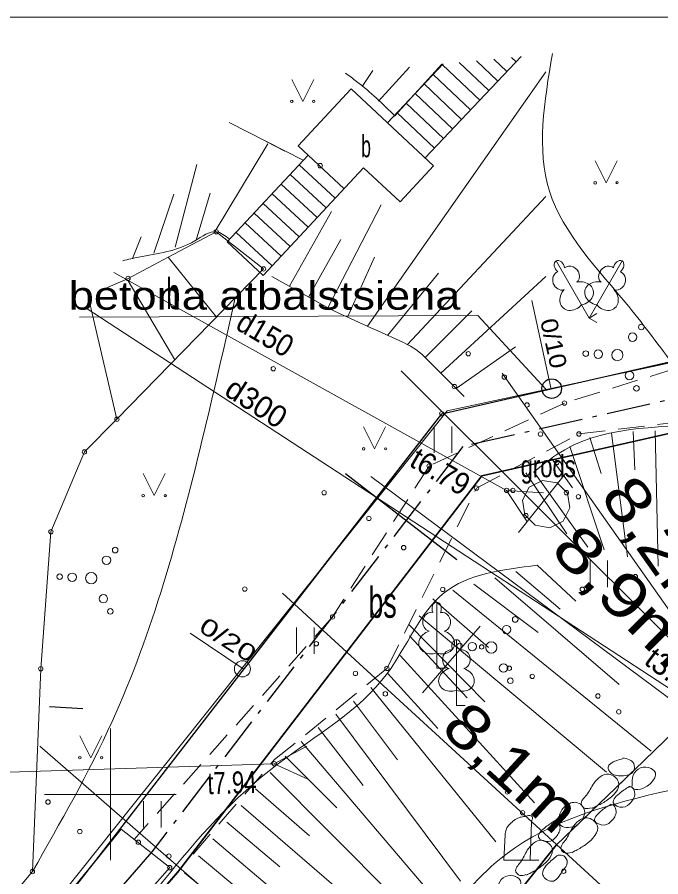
# Model space of a CAD drawing. Extents: x -1271.1 to -1218.8, y 769 to 838.3.
# Drawn here: x -1247.62 to -1232.98, y 818.71 to 838.28 of the extents above; entities that cross this region are included whole.
import ezdxf
from ezdxf.enums import TextEntityAlignment as Align

# ---------------------------------------------------------------- set-up
doc = ezdxf.new("R2010")
doc.units = 0
doc.header["$LTSCALE"] = 0.2
doc.linetypes.add('DOT_DASHED', pattern=[7.7, 5, -1.2, 0.3, -1.2])
doc.linetypes.add('MEDIUM_DASHED', pattern=[4.5, 3, -1.5])
for name, color, linetype, lineweight in [('1', 7, 'Continuous', 13), ('19', 7, 'Continuous', 13), ('25', 7, 'Continuous', 13), ('28', 7, 'Continuous', 13), ('3', 7, 'Continuous', 13), ('30', 7, 'Continuous', 13), ('35', 7, 'Continuous', 25), ('5', 7, 'Continuous', 13), ('55', 7, 'Continuous', 13), ('56', 7, 'Continuous', 13), ('6', 7, 'Continuous', 13), ('61', 7, 'Continuous', 13), ('62', 7, 'Continuous', 13), ('63', 7, 'Continuous', 13)]:
    doc.layers.add(name, color=color, linetype=linetype, lineweight=lineweight)
for name, color, linetype in [('10', 7, 'Continuous'), ('11', 7, 'Continuous'), ('15', 7, 'Continuous')]:
    doc.layers.add(name, color=color, linetype=linetype)

msp = doc.modelspace()

# ---------------------------------------------------------------- linework, layer by layer
at = {"layer": '1'}
for p, q in [((-1239.776, 836.7), (-1239.532, 837.06)), ((-1239.406, 836.364), (-1238.704, 837.139)), ((-1239.036, 836.028), (-1237.965, 837.209)), ((-1239.653, 831.243), (-1235.601, 837.032)), ((-1243.118, 833.404), (-1241.924, 835.396)), ((-1244.033, 833.046), (-1243.542, 834.922)), ((-1244.513, 832.907), (-1244.059, 834.249)), ((-1243.557, 833.198), (-1243.234, 834.273)), ((-1238.745, 830.824), (-1235.601, 834.194)), ((-1240.56, 831.663), (-1239.347, 834.009)), ((-1241.432, 832.152), (-1240.476, 833.853)), ((-1244.998, 832.783), (-1244.803, 833.279)), ((-1240.996, 831.907), (-1240.261, 833.214)), ((-1240.109, 831.447), (-1239.498, 832.816)), ((-1239.198, 831.035), (-1238.041, 832.447)), ((-1237.99, 830.176), (-1235.601, 832.375)), ((-1235.485, 829.842), (-1235.921, 831.825)), ((-1238.343, 830.529), (-1237.283, 831.591)), ((-1237.636, 829.823), (-1236.293, 830.774)), ((-1238.894, 830.226), (-1231.002, 822.353)), ((-1228.446, 818.593), (-1236.594, 830.173)), ((-1233.61, 828.848), (-1233.573, 827.973)), ((-1233.11, 828.861), (-1233.048, 825.785)), ((-1234.598, 828.708), (-1234.344, 827.894)), ((-1234.109, 828.809), (-1233.743, 825.994)), ((-1235.054, 828.507), (-1234.271, 826.156)), ((-1235.464, 828.221), (-1234.996, 827.565)), ((-1235.871, 827.931), (-1234.647, 826.214)), ((-1239.581, 827.819), (-1230.198, 820.844)), ((-1235.8, 825.801), (-1234.915, 824.985)), ((-1236.759, 825.516), (-1233.93, 823.086)), ((-1236.28, 825.659), (-1235.273, 824.806)), ((-1237.238, 825.374), (-1235.775, 824.269)), ((-1241.586, 825.164), (-1230.918, 815.373)), ((-1237.718, 825.232), (-1233.202, 821.569)), ((-1238.174, 825.038), (-1236.903, 823.928)), ((-1238.484, 824.65), (-1234.223, 821.091)), ((-1242.465, 823.426), (-1243.688, 824.26)), ((-1238.698, 824.198), (-1237.386, 822.782)), ((-1238.91, 823.745), (-1235.858, 820.396)), ((-1239.205, 823.344), (-1238.058, 822.089)), ((-1239.583, 823.017), (-1236.735, 819.506)), ((-1239.977, 822.71), (-1238.971, 821.376)), ((-1240.377, 822.41), (-1237.544, 818.612)), ((-1240.776, 822.109), (-1239.755, 820.789)), ((-1241.164, 821.793), (-1238.014, 818.09)), ((-1247.111, 821.685), (-1235.538, 811.611)), ((-1241.532, 821.455), (-1240.352, 820.28)), ((-1241.871, 821.088), (-1238.432, 817.627)), ((-1242.202, 820.713), (-1240.977, 819.642)), ((-1242.53, 820.335), (-1238.852, 817.164)), ((-1242.855, 819.955), (-1241.653, 818.938)), ((-1243.178, 819.573), (-1239.485, 816.469)), ((-1243.499, 819.19), (-1242.327, 818.215)), ((-1243.818, 818.805), (-1240.142, 815.757))]:
    msp.add_line(p, q, dxfattribs=at)
msp.add_lwpolyline([(-1237.459, 829.646), (-1237.914, 830.1), (-1238.369, 830.555), (-1238.424, 830.606), (-1238.478, 830.651), (-1238.53, 830.691), (-1238.581, 830.726), (-1238.679, 830.787), (-1238.769, 830.837), (-1238.849, 830.877), (-1239.425, 831.137), (-1239.58, 831.21), (-1240.128, 831.455), (-1240.264, 831.517), (-1240.466, 831.615), (-1240.565, 831.666), (-1240.664, 831.72), (-1241.247, 832.048), (-1241.829, 832.375)], dxfattribs=at)
at = {"layer": '1', "lineweight": 25}
msp.add_circle((-1235.466, 829.823), 0.2224, dxfattribs=at)
at = {"layer": '1'}
msp.add_circle((-1242.502, 823.444), 0.1827, dxfattribs=at)
for points in [[(-1240.158, 837.001), (-1239.903, 836.815), (-1239.03, 836.023)], [(-1245.222, 832.735), (-1244.862, 832.816), (-1243.584, 833.187), (-1243.096, 833.394), (-1242.798, 833.227)], [(-1235.871, 827.931), (-1235.167, 828.433), (-1231.672, 829.028), (-1224.12, 831.442)], [(-1235.8, 825.801), (-1237.913, 825.174), (-1239.203, 823.346), (-1241.709, 821.268), (-1246.557, 815.58), (-1256.526, 805.053), (-1260.592, 799.147), (-1261.416, 795.29), (-1262.742, 791.444), (-1262.206, 785.139)]]:
    msp.add_spline(points, degree=3, dxfattribs=at)
at = {"layer": '19'}
msp.add_spline([(-1253.457, 785.393), (-1253.726, 794.104), (-1251.637, 801.373), (-1250.122, 804.26), (-1247.608, 807.348), (-1239.437, 815.545), (-1236.508, 819.221), (-1228.799, 821.851), (-1223.357, 826.161), (-1220.079, 827.95)], degree=3, dxfattribs=at)
at = {"layer": '25'}
for points in [[(-1245.505, 822.086), (-1245.505, 820.586), (-1245.505, 819.086)], [(-1245.505, 822.086), (-1245.505, 820.586), (-1245.505, 819.086)], [(-1247.005, 820.586), (-1245.505, 820.586), (-1244.005, 820.586)], [(-1247.005, 820.586), (-1245.505, 820.586), (-1244.005, 820.586)]]:
    msp.add_lwpolyline(points, dxfattribs=at)
at = {"layer": '28'}
for points in [[(-1235.654, 827.452), (-1236.491, 827.506), (-1236.033, 826.804)], [(-1241.04, 821.682), (-1241.778, 821.284), (-1241.017, 820.933)]]:
    msp.add_lwpolyline(points, dxfattribs=at)
at = {"layer": '3'}
for p, q in [((-1236.491, 827.506), (-1245.43, 832.464)), ((-1232.369, 822.724), (-1246.052, 831.654)), ((-1251.16, 820.99), (-1241.778, 821.284))]:
    msp.add_line(p, q, dxfattribs=at)
at = {"layer": '30'}
msp.add_spline([(-1247.278, 818.829), (-1245.467, 822.244), (-1243.421, 828.633), (-1242.663, 831.887)], degree=3, dxfattribs=at)
at = {"layer": '35'}
msp.add_lwpolyline([(-1264.692, 791.666), (-1263.121, 794.463), (-1262.995, 800.82), (-1256.407, 807.512), (-1249.819, 814.203), (-1245.888, 819.015), (-1242.275, 823.687), (-1240.604, 825.846), (-1237.968, 829.25), (-1236.511, 829.583), (-1228.03, 831.521)], dxfattribs=at)
at = {"layer": '35', "lineweight": 35}
msp.add_lwpolyline([(-1225.362, 830.487), (-1237.056, 827.834), (-1243.981, 818.809), (-1250.833, 810.905), (-1258.147, 803.474), (-1260.339, 800.099), (-1261.472, 796.156), (-1261.529, 794.093), (-1263.29, 790.894)], dxfattribs=at)
at = {"layer": '5'}
for p, q in [((-1235.366, 832.728), (-1234.79, 831.73)), ((-1235.172, 832.572), (-1235.174, 832.572)), ((-1233.866, 832.728), (-1234.443, 831.73)), ((-1233.905, 832.482), (-1233.905, 832.483)), ((-1234.79, 831.73), (-1234.616, 831.429)), ((-1234.443, 831.73), (-1234.616, 831.429)), ((-1234.616, 831.429), (-1234.443, 831.529)), ((-1234.616, 831.429), (-1234.443, 831.329)), ((-1238.137, 828.361), (-1238.137, 828.961)), ((-1237.737, 828.361), (-1237.737, 828.961)), ((-1234.594, 825.307), (-1234.594, 825.907)), ((-1234.194, 825.307), (-1234.194, 825.907)), ((-1238.083, 824.961), (-1238.083, 823.808)), ((-1237.993, 824.729), (-1237.994, 824.73)), ((-1241.27, 823.783), (-1241.27, 824.383)), ((-1240.87, 823.783), (-1240.87, 824.383)), ((-1237.633, 824.107), (-1237.633, 822.954)), ((-1238.083, 823.808), (-1238.083, 823.461)), ((-1237.543, 823.875), (-1237.544, 823.876)), ((-1238.083, 823.461), (-1237.883, 823.461)), ((-1237.633, 822.954), (-1237.633, 822.607)), ((-1237.633, 822.607), (-1237.433, 822.607)), ((-1244.748, 819.833), (-1244.748, 820.433)), ((-1244.348, 819.833), (-1244.348, 820.433)), ((-1235.958, 819.092), (-1235.924, 819.957)), ((-1235.958, 819.092), (-1236.558, 819.092)), ((-1235.958, 819.092), (-1235.758, 819.092))]:
    msp.add_line(p, q, dxfattribs=at)
for points in [[(-1241.378, 836.861), (-1241.128, 836.361), (-1240.878, 836.861)], [(-1234.477, 835.008), (-1234.227, 834.508), (-1233.977, 835.008)], [(-1239.744, 828.953), (-1239.494, 828.453), (-1239.244, 828.953)], [(-1244.758, 827.887), (-1244.508, 827.387), (-1244.258, 827.887)], [(-1246.2, 821.922), (-1245.95, 821.422), (-1245.7, 821.922)], [(-1236.527, 819.665), (-1236.558, 819.092), (-1236.258, 819.092), (-1235.958, 819.092)]]:
    msp.add_lwpolyline(points, dxfattribs=at)
for centre, radius in [((-1241.3784, 836.3607), 0.028), ((-1240.8784, 836.3607), 0.0263), ((-1234.4776, 834.5072), 0.028), ((-1233.9776, 834.5072), 0.0263), ((-1233.429, 831.2245), 0.064), ((-1233.6255, 830.9928), 0.096), ((-1234.6915, 830.6194), 0.064), ((-1234.407, 830.6059), 0.096), ((-1233.973, 830.5851), 0.128), ((-1233.6966, 830.1183), 0.096), ((-1233.5391, 829.829), 0.064), ((-1239.7447, 828.4523), 0.028), ((-1239.2447, 828.4523), 0.0263), ((-1244.7584, 827.3863), 0.028), ((-1244.2584, 827.3863), 0.0263), ((-1245.396, 826.1475), 0.064), ((-1245.5925, 825.9158), 0.096), ((-1246.6584, 825.5424), 0.064), ((-1246.374, 825.5289), 0.096), ((-1245.94, 825.5082), 0.128), ((-1245.6636, 825.0413), 0.096), ((-1245.5061, 824.752), 0.064), ((-1236.296, 824.5695), 0.064), ((-1236.4925, 824.3378), 0.096), ((-1237.5584, 823.9644), 0.064), ((-1237.274, 823.9509), 0.096), ((-1236.84, 823.9302), 0.128), ((-1236.5636, 823.4633), 0.096), ((-1236.4061, 823.174), 0.064), ((-1246.1999, 821.4214), 0.028), ((-1245.6999, 821.4214), 0.0263)]:
    msp.add_circle(centre, radius, dxfattribs=at)
for centre, major_axis, ratio, start_param, end_param in [((-1235.2914, 832.5981), (0.075, -0.1298), 0.707107, 0.9957007, 3.1378155), ((-1233.9407, 832.5981), (-0.075, -0.1298), 0.707107, 3.1453698, 5.2874846), ((-1235.2907, 832.5985), (0.075, -0.1298), 0.707107, 3.1453698, 5.2874846), ((-1235.0325, 832.4071), (0.1397, -0.1646), 0.861323, 6.2831853, 9.424778), ((-1234.1996, 832.4071), (-0.1397, -0.1646), 0.861323, 3.1415927, 6.2831853), ((-1233.9414, 832.5985), (-0.075, -0.1298), 0.707107, 0.9957007, 3.1378155), ((-1235.2548, 832.2788), (0.0727, -0.2033), 0.861323, 3.1415927, 6.2831853), ((-1233.9773, 832.2788), (-0.0727, -0.2033), 0.861323, 6.2831853, 9.424778), ((-1234.8349, 831.9874), (-0.3133, -0.071), 0.814445, 1.5311707, 4.712389), ((-1234.3972, 831.9874), (0.3133, -0.071), 0.814445, 1.5707963, 4.7520146), ((-1234.9901, 831.8978), (0.2182, 0.2358), 0.814445, 1.5707963, 4.7520146), ((-1234.242, 831.8978), (-0.2182, 0.2358), 0.814445, 1.5311707, 4.712389), ((-1238.0826, 824.8112), (0, -0.1499), 0.707107, 3.1453698, 5.2874846), ((-1238.0835, 824.8112), (0, -0.1499), 0.707107, 0.9957007, 3.1378155), ((-1238.2113, 824.5164), (-0.0387, -0.2124), 0.861323, 3.1415927, 6.2831853), ((-1237.9548, 824.5164), (0.0387, -0.2124), 0.861323, 6.2831853, 9.424778), ((-1238.1726, 824.0541), (0.3068, 0.0951), 0.814445, 1.5707963, 4.7520146), ((-1237.9935, 824.0541), (-0.3068, 0.0951), 0.814445, 1.5311707, 4.712389), ((-1237.6326, 823.9572), (0, -0.1499), 0.707107, 3.1453698, 5.2874846), ((-1237.6335, 823.9572), (0, -0.1499), 0.707107, 0.9957007, 3.1378155), ((-1237.7613, 823.6624), (-0.0387, -0.2124), 0.861323, 3.1415927, 6.2831853), ((-1237.5048, 823.6624), (0.0387, -0.2124), 0.861323, 6.2831853, 9.424778), ((-1237.7226, 823.2001), (0.3068, 0.0951), 0.814445, 1.5707963, 4.7520146), ((-1237.5435, 823.2001), (-0.3068, 0.0951), 0.814445, 1.5311707, 4.712389)]:
    msp.add_ellipse(centre, major_axis=major_axis, ratio=ratio, start_param=start_param, end_param=end_param, dxfattribs=at)
msp.add_spline([(-1235.924, 819.957), (-1235.92, 819.988), (-1235.917, 819.999), (-1235.902, 820.061), (-1235.932, 820.096), (-1236.054, 820.09), (-1236.158, 820.072), (-1236.264, 820.033), (-1236.329, 819.989), (-1236.404, 819.925), (-1236.484, 819.827), (-1236.515, 819.738), (-1236.527, 819.664)], degree=3, dxfattribs=at)
at = {"layer": '55'}
msp.add_lwpolyline([(-1264.692, 791.666), (-1263.121, 794.463), (-1263.06, 799.299), (-1247.785, 816.834), (-1237.845, 829.32), (-1225.799, 831.912), (-1223.768, 834.184)], dxfattribs=at)
at = {"layer": '56'}
for p, q in [((-1238.348, 835.073), (-1236.164, 837.38)), ((-1236.897, 836.605), (-1237.574, 837.246)), ((-1236.691, 836.823), (-1237.177, 837.284)), ((-1236.484, 837.041), (-1236.78, 837.321)), ((-1236.278, 837.259), (-1236.383, 837.359)), ((-1239.204, 835.872), (-1237.935, 837.212)), ((-1237.103, 836.387), (-1237.953, 837.192)), ((-1237.31, 836.17), (-1238.16, 836.975)), ((-1237.516, 835.952), (-1238.366, 836.757)), ((-1241.237, 835.352), (-1240.03, 836.644)), ((-1240.03, 836.644), (-1238.152, 834.89)), ((-1237.722, 835.734), (-1238.572, 836.539)), ((-1237.928, 835.516), (-1238.778, 836.321)), ((-1238.135, 835.298), (-1238.985, 836.103)), ((-1241.237, 835.352), (-1240.189, 834.373)), ((-1241.004, 835.134), (-1242.847, 833.161)), ((-1241.209, 834.915), (-1240.394, 834.154)), ((-1238.915, 834.072), (-1238.152, 834.89)), ((-1242.032, 832.4), (-1239.746, 834.847)), ((-1241.414, 834.696), (-1240.599, 833.935)), ((-1238.915, 834.072), (-1239.746, 834.847)), ((-1241.619, 834.477), (-1240.804, 833.716)), ((-1241.823, 834.257), (-1241.008, 833.496)), ((-1242.028, 834.038), (-1241.213, 833.277)), ((-1242.233, 833.819), (-1241.418, 833.058)), ((-1242.438, 833.6), (-1241.623, 832.839)), ((-1242.642, 833.38), (-1241.827, 832.619)), ((-1242.847, 833.161), (-1242.032, 832.4))]:
    msp.add_line(p, q, dxfattribs=at)
for points in [[(-1236.131, 827.282), (-1236.079, 826.949), (-1235.842, 826.711), (-1235.51, 826.657), (-1235.209, 826.809), (-1235.056, 827.108), (-1235.107, 827.441), (-1235.344, 827.679), (-1235.677, 827.733), (-1235.977, 827.581)], [(-1247.583, 816.91), (-1246.86, 816.313), (-1245.222, 817.711), (-1244.154, 818.919), (-1245.261, 819.794)]]:
    msp.add_lwpolyline(points, close=True, dxfattribs=at)
at = {"layer": '6'}
for centre in [(-1240.733, 834.8972), (-1243.096, 833.3942), (-1242.02, 832.5462), (-1245.103, 832.3322), (-1237.3636, 830.6165), (-1241.799, 830.2752), (-1236.5437, 830.0864), (-1237.678, 829.8682), (-1236.027, 829.4511), (-1235.176, 829.4941), (-1237.968, 829.2502), (-1245.357, 829.1252), (-1235.721, 828.7871), (-1234.848, 828.7902), (-1246.095, 828.3812), (-1238.254, 828.0592), (-1235.35, 828.1431), (-1240.6432, 827.4527), (-1237.177, 827.5582), (-1236.491, 827.5062), (-1236.348, 827.5052), (-1235.131, 827.4542), (-1234.86, 827.3612), (-1239.625, 826.8672), (-1236.053, 826.9322), (-1246.858, 826.5642), (-1238.834, 826.2022), (-1233.564, 825.5442), (-1242.4472, 825.2601), (-1234.77, 825.2542), (-1237.944, 825.2512), (-1240.45, 824.6272), (-1240.82, 824.0152), (-1237.059, 823.9422), (-1247.088, 823.4472), (-1239.93, 823.3392), (-1239.214, 823.4532), (-1236.43, 823.4572), (-1235.909, 823.2722), (-1239.251, 822.8752), (-1234.414, 822.8261), (-1233.9405, 822.4659), (-1237.777, 821.9182), (-1241.778, 821.2841), (-1236.474, 820.6431), (-1246.9232, 820.4134), (-1236.129, 820.1692), (-1246.2, 819.7412), (-1244.869, 819.4961), (-1244.173, 819.1811), (-1247.278, 818.8292), (-1244.154, 818.9192), (-1235.193, 818.8372)]:
    msp.add_circle(centre, 0.05, dxfattribs=at)
at = {"layer": '61'}
msp.add_lwpolyline([(-1249.819, 814.203), (-1246.581, 818.124), (-1237.968, 829.25), (-1225.679, 832.058)], dxfattribs=at)
at = {"layer": '62'}
for p, q in [((-1241.123, 835.019), (-1242.806, 835.88)), ((-1241.959, 835.451), (-1241.537, 835.228))]:
    msp.add_line(p, q, dxfattribs=at)
msp.add_spline([(-1235.451, 837.447), (-1235.516, 834.318), (-1233.714, 831.689), (-1232.669, 830.321)], degree=3, dxfattribs=at)
at = {"layer": '63'}
for p, q in [((-1244.191, 832.814), (-1243.088, 831.451)), ((-1245.103, 832.279), (-1244.037, 830.479)), ((-1245.357, 829.125), (-1245.971, 831.759)), ((-1235.154, 827.889), (-1236.223, 826.551)), ((-1236.056, 827.906), (-1235.12, 826.518)), ((-1238.713, 824.453), (-1236.99, 822.696)), ((-1237.092, 824.419), (-1238.409, 822.899))]:
    msp.add_line(p, q, dxfattribs=at)
at = {"layer": '63', "lineweight": 25}
for p, q in [((-1240.156, 827.892), (-1237.623, 825.936)), ((-1246.893, 822.588), (-1246.13, 822.539))]:
    msp.add_line(p, q, dxfattribs=at)
at = {"layer": '63'}
for points in [[(-1218.845, 838.277), (-1268.854, 838.277), (-1268.854, 768.981)], [(-1256.412, 818.123), (-1256.201, 815.29), (-1252.408, 813.098), (-1251.504, 813.774), (-1247.278, 818.829), (-1247.088, 823.447), (-1246.858, 826.564), (-1246.095, 828.381), (-1245.357, 829.125), (-1242.02, 832.546), (-1243.096, 833.394)], [(-1243.096, 833.394), (-1244.191, 832.814), (-1245.103, 832.332), (-1245.747, 832.051)], [(-1246.211, 831.447), (-1237.143, 831.487), (-1235.598, 829.809)]]:
    msp.add_lwpolyline(points, dxfattribs=at)
at = {"layer": '63', "linetype": 'MEDIUM_DASHED'}
for points in [[(-1225.119, 832.074), (-1232.655, 830.279), (-1235.176, 829.494), (-1238.254, 828.059), (-1240.45, 824.627), (-1244.967, 819.561)], [(-1265.079, 785.987), (-1263.807, 789.442), (-1261.536, 795.397), (-1260.86, 799.605), (-1256.627, 805.136), (-1246.564, 815.823), (-1241.769, 821.378), (-1239.214, 823.453), (-1237.177, 827.558), (-1234.848, 828.79), (-1231.517, 829.195), (-1224.557, 831.447)]]:
    msp.add_lwpolyline(points, dxfattribs=at)
at = {"layer": '63', "linetype": 'DOT_DASHED', "lineweight": 25}
for points in [[(-1225.528, 831.218), (-1237.486, 828.505), (-1244.562, 819.283), (-1251.384, 811.414), (-1258.735, 803.946), (-1261.029, 800.414), (-1262.219, 796.272), (-1262.274, 794.295), (-1264.33, 790.56), (-1266.742, 787.222)], [(-1254.918, 786.26), (-1254.605, 794.542), (-1253.865, 797.042), (-1252.437, 799.553), (-1250.698, 801.658), (-1245.95, 807.041), (-1239.139, 814.697), (-1235.363, 819.429), (-1232.239, 822.444), (-1231.619, 822.931), (-1231.44, 822.991), (-1229.31, 823.677), (-1223.125, 826.536)]]:
    msp.add_lwpolyline(points, dxfattribs=at)
at = {"layer": '63', "lineweight": 35}
msp.add_lwpolyline([(-1254.918, 786.26), (-1254.605, 794.542), (-1253.865, 797.042), (-1252.437, 799.553), (-1251.568, 800.606), (-1250.698, 801.658), (-1248.324, 804.35), (-1245.95, 807.041), (-1242.544, 810.869), (-1239.139, 814.697), (-1237.251, 817.063), (-1235.363, 819.429), (-1233.801, 820.936), (-1232.239, 822.444), (-1231.619, 822.931), (-1229.31, 823.677), (-1223.125, 826.536)], dxfattribs=at)
at = {"layer": '63'}
for points in [[(-1233.847, 821.42), (-1233.601, 821.289), (-1233.607, 821.114), (-1233.871, 821.008), (-1234.135, 821.09), (-1234.183, 821.205), (-1234.011, 821.352), (-1233.839, 821.402)], [(-1233.638, 820.775), (-1233.61, 821.027), (-1233.446, 821.19), (-1233.205, 821.174), (-1233.107, 821.074), (-1233.196, 820.861), (-1233.337, 820.748), (-1233.562, 820.699), (-1233.638, 820.726)], [(-1234.566, 820.281), (-1234.705, 820.269), (-1234.792, 820.358), (-1234.676, 820.569), (-1234.511, 820.834), (-1234.17, 821.046), (-1233.945, 820.867), (-1234.225, 820.442), (-1234.452, 820.318), (-1234.554, 820.268)], [(-1233.689, 820.773), (-1233.898, 820.63), (-1234.066, 820.395), (-1233.848, 820.295), (-1233.664, 820.404), (-1233.58, 820.639), (-1233.655, 820.756), (-1233.714, 820.756)], [(-1234.774, 820.01), (-1234.716, 820.176), (-1234.876, 820.397), (-1235.114, 820.35), (-1235.281, 820.143), (-1235.26, 819.878), (-1235.082, 819.835), (-1234.931, 819.866)], [(-1234.113, 820.368), (-1234.322, 820.225), (-1234.49, 819.99), (-1234.272, 819.89), (-1234.088, 819.999), (-1234.004, 820.234), (-1234.079, 820.351), (-1234.138, 820.351)], [(-1235.025, 819.271), (-1235.163, 819.253), (-1235.254, 819.338), (-1235.148, 819.554), (-1234.995, 819.826), (-1234.663, 820.053), (-1234.431, 819.884), (-1234.691, 819.447), (-1234.913, 819.313), (-1235.012, 819.258)], [(-1235.388, 819.991), (-1235.597, 819.848), (-1235.765, 819.613), (-1235.547, 819.513), (-1235.363, 819.622), (-1235.279, 819.857), (-1235.354, 819.974), (-1235.413, 819.974)], [(-1236.053, 818.76), (-1236.191, 818.742), (-1236.282, 818.827), (-1236.176, 819.043), (-1236.023, 819.315), (-1235.691, 819.542), (-1235.459, 819.373), (-1235.719, 818.936), (-1235.941, 818.802), (-1236.04, 818.747)], [(-1235.32, 819.205), (-1235.54, 819.02), (-1235.667, 818.751), (-1235.461, 818.608), (-1235.217, 818.844), (-1235.112, 819.038), (-1235.193, 819.185), (-1235.32, 819.205)], [(-1236.692, 818.294), (-1236.676, 818.547), (-1236.519, 818.717), (-1236.278, 818.712), (-1236.175, 818.616), (-1236.255, 818.399), (-1236.39, 818.28), (-1236.613, 818.221), (-1236.69, 818.245)]]:
    msp.add_spline(points, degree=3, dxfattribs=at)

# ---------------------------------------------------------------- texts
at = {"layer": '1'}
for s, rotation, width, p in [('0/10', 282.385, 1.15, (-1235.6077, 830.8117)), ('0/20', 327.602, 1.4, (-1242.9319, 823.9429))]:
    msp.add_text(s, height=0.384, rotation=rotation, dxfattribs=dict(at, width=width)).set_placement(p, align=Align.CENTER)
at = {"layer": '10'}
for s, width, p in [('b', 0.6, (-1244.0765, 831.637)), ('bs', 0.65, (-1239.313, 824.607))]:
    msp.add_text(s, height=0.7, dxfattribs=dict(at, width=width)).set_placement(p, align=Align.CENTER)
at = {"layer": '11'}
for s, rotation, width, p in [('d150', 329.713, 0.9, (-1242.1071, 830.8545)), ('t6.79', 329.713, 0.95, (-1238.1241, 827.7202)), ('t7.94', 1.795, 0.75, (-1242.7328, 820.6057))]:
    msp.add_text(s, height=0.5, rotation=rotation, dxfattribs=dict(at, width=width)).set_placement(p, align=Align.CENTER)
for s, rotation, p in [('d300', 327.224, (-1242.3198, 829.2935)), ('t3.99', 323.042, (-1232.8003, 823.1276))]:
    msp.add_text(s, height=0.5, rotation=rotation, dxfattribs=at).set_placement(p, align=Align.CENTER)
at = {"layer": '15'}
for s, width, p in [('b', 0.6, (-1239.801, 835.088)), ('grods', 0.75, (-1236.173, 827.806))]:
    msp.add_text(s, height=0.5, dxfattribs=dict(at, width=width)).set_placement(p)
at = {"layer": '63', "width": 1.2}
msp.add_text('betona atbalstsiena', height=0.64, dxfattribs=at).set_placement((-1241.998, 831.62), align=Align.CENTER)
at = {"layer": '63'}
for s, rotation, width, p in [('8,2m', 305.131, 1.25, (-1233.3202, 825.8562)), ('8,9m', 315.069, 1.3, (-1234.1616, 824.746)), ('8,1m', 317.455, 1.2, (-1236.7086, 820.8379))]:
    msp.add_text(s, height=1, rotation=rotation, dxfattribs=dict(at, width=width)).set_placement(p, align=Align.CENTER)

doc.saveas('drawing.dxf')
